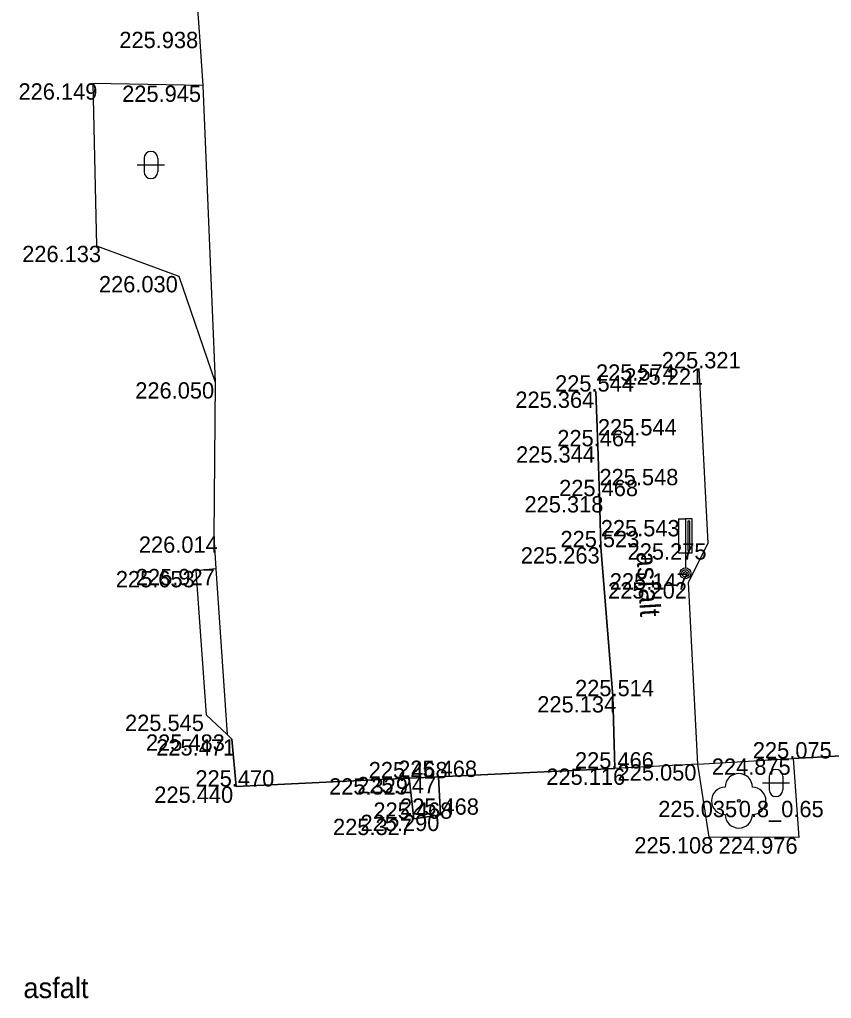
# Model space of a CAD drawing. Extents: x -599516 to -599132, y -1163668 to -1163119.
# Drawn here: x -599367.22 to -599352.29, y -1163237.29 to -1163219.3 of the extents above; entities that cross this region are included whole.
import ezdxf

# ---------------------------------------------------------------- set-up
doc = ezdxf.new("R2010")
doc.units = 0
for name, color, linetype in [('Bod-oznac1', 7, 'Continuous'), ('Bod-oznac2', 7, 'Continuous'), ('Bod-oznac3', 7, 'Continuous'), ('Bod-vyska1', 7, 'Continuous'), ('Bod-vyska2', 7, 'Continuous'), ('Bod-vyska3', 7, 'Continuous'), ('Z_cela-hrobu-dolni-linie', 7, 'Continuous'), ('Z_cela-hrobu-horni-linie', 7, 'Continuous'), ('Z_chodnik', 7, 'Continuous'), ('Z_komunikace', 7, 'Continuous'), ('Z_kultury-znacky', 7, 'Continuous'), ('Z_obvod-kmene-spodek-ve-vysce1_2m', 7, 'Continuous'), ('Z_popis-budov-povrchu', 7, 'Continuous'), ('Z_stromy-kere', 7, 'Continuous'), ('Z_zelen-obvod-zivy-plot', 7, 'Continuous'), ('Z_znacky-ostatni-orientacni-sloupek', 7, 'Continuous'), ('Z_zpevnene-plochy', 7, 'Continuous')]:
    doc.layers.add(name, color=color, linetype=linetype)

msp = doc.modelspace()

# ---------------------------------------------------------------- linework, layer by layer
at = {"layer": 'Bod-oznac1'}
for p, q in [((-599363.911, -1163219.523), (-599363.911, -1163219.523)), ((-599365.869, -1163220.47), (-599365.869, -1163220.47)), ((-599363.848, -1163220.511), (-599363.848, -1163220.511)), ((-599365.801, -1163223.457), (-599365.801, -1163223.457)), ((-599364.29, -1163224.012), (-599364.29, -1163224.012)), ((-599354.719, -1163225.709), (-599354.719, -1163225.709)), ((-599363.622, -1163225.965), (-599363.622, -1163225.965)), ((-599356.618, -1163226.136), (-599356.618, -1163226.136)), ((-599356.583, -1163227.142), (-599356.583, -1163227.142)), ((-599356.554, -1163228.058), (-599356.554, -1163228.058)), ((-599363.646, -1163228.799), (-599363.646, -1163228.799)), ((-599356.53, -1163228.997), (-599356.53, -1163228.997)), ((-599354.553, -1163228.925), (-599354.553, -1163228.925)), ((-599363.976, -1163229.434), (-599363.976, -1163229.434)), ((-599363.605, -1163229.396), (-599363.605, -1163229.396)), ((-599354.973, -1163229.475), (-599354.973, -1163229.475)), ((-599354.916, -1163229.641), (-599354.916, -1163229.641)), ((-599356.308, -1163231.735), (-599356.308, -1163231.735)), ((-599363.783, -1163232.075), (-599363.783, -1163232.075)), ((-599363.398, -1163232.438), (-599363.398, -1163232.438)), ((-599363.312, -1163232.527), (-599363.312, -1163232.527)), ((-599352.993, -1163232.88), (-599352.993, -1163232.88)), ((-599356.269, -1163233.065), (-599356.269, -1163233.065)), ((-599354.743, -1163232.987), (-599354.743, -1163232.987)), ((-599360.055, -1163233.244), (-599360.055, -1163233.244)), ((-599359.514, -1163233.22), (-599359.514, -1163233.22)), ((-599363.236, -1163233.396), (-599363.236, -1163233.396)), ((-599353.993, -1163233.659), (-599353.993, -1163233.659)), ((-599359.969, -1163233.988), (-599359.969, -1163233.988)), ((-599359.479, -1163233.914), (-599359.479, -1163233.914)), ((-599354.536, -1163234.326), (-599354.536, -1163234.326)), ((-599352.89, -1163234.332), (-599352.89, -1163234.332))]:
    msp.add_line(p, q, dxfattribs=at)
at = {"layer": 'Bod-oznac2'}
for p, q in [((-599354.719, -1163225.709), (-599354.719, -1163225.709)), ((-599356.618, -1163226.136), (-599356.618, -1163226.136)), ((-599356.583, -1163227.142), (-599356.583, -1163227.142)), ((-599356.554, -1163228.058), (-599356.554, -1163228.058)), ((-599356.53, -1163228.997), (-599356.53, -1163228.997)), ((-599356.308, -1163231.735), (-599356.308, -1163231.735)), ((-599352.993, -1163232.88), (-599352.993, -1163232.88)), ((-599356.269, -1163233.065), (-599356.269, -1163233.065)), ((-599360.055, -1163233.244), (-599360.055, -1163233.244)), ((-599359.514, -1163233.22), (-599359.514, -1163233.22)), ((-599363.236, -1163233.396), (-599363.236, -1163233.396)), ((-599359.969, -1163233.988), (-599359.969, -1163233.988)), ((-599359.479, -1163233.914), (-599359.479, -1163233.914))]:
    msp.add_line(p, q, dxfattribs=at)
at = {"layer": 'Bod-oznac3'}
for p, q in [((-599356.618, -1163226.136), (-599356.618, -1163226.136)), ((-599356.583, -1163227.142), (-599356.583, -1163227.142)), ((-599356.554, -1163228.058), (-599356.554, -1163228.058)), ((-599356.53, -1163228.997), (-599356.53, -1163228.997))]:
    msp.add_line(p, q, dxfattribs=at)
at = {"layer": 'Z_cela-hrobu-dolni-linie'}
for p, q in [((-599363.848, -1163220.511), (-599363.622, -1163225.965)), ((-599354.743, -1163232.987), (-599352.993, -1163232.88))]:
    msp.add_line(p, q, dxfattribs=at)
msp.add_lwpolyline([(-599359.514, -1163233.22), (-599360.055, -1163233.244)], dxfattribs=at)
at = {"layer": 'Z_cela-hrobu-horni-linie'}
msp.add_line((-599354.553, -1163228.925), (-599354.719, -1163225.709), dxfattribs=at)
for points in [[(-599363.312, -1163232.527), (-599363.236, -1163233.396), (-599360.055, -1163233.244), (-599359.514, -1163233.22), (-599356.269, -1163233.065), (-599356.308, -1163231.735), (-599356.53, -1163228.997), (-599356.53, -1163228.997), (-599356.554, -1163228.058), (-599356.554, -1163228.058), (-599356.583, -1163227.142), (-599356.583, -1163227.142), (-599356.618, -1163226.136), (-599356.618, -1163226.136)], [(-599354.743, -1163232.987), (-599352.993, -1163232.88), (-599348.121, -1163232.614), (-599348.121, -1163232.614)]]:
    msp.add_lwpolyline(points, dxfattribs=at)
at = {"layer": 'Z_chodnik'}
msp.add_line((-599354.743, -1163232.987), (-599354.916, -1163229.641), dxfattribs=at)
for points in [[(-599354.916, -1163229.641), (-599354.553, -1163228.925), (-599354.719, -1163225.709)], [(-599356.618, -1163226.136), (-599356.583, -1163227.142), (-599356.554, -1163228.058), (-599356.53, -1163228.997), (-599356.308, -1163231.735)], [(-599356.308, -1163231.735), (-599356.269, -1163233.065)]]:
    msp.add_lwpolyline(points, dxfattribs=at)
at = {"layer": 'Z_komunikace'}
msp.add_line((-599363.236, -1163233.396), (-599363.312, -1163232.527), dxfattribs=at)
for points in [[(-599364.81, -1163202.525), (-599364.713, -1163204.27), (-599364.649, -1163207.2), (-599364.55, -1163208.52), (-599365.622, -1163208.83), (-599366.647, -1163211.3), (-599366.029, -1163213.009), (-599364.308, -1163212.853), (-599364.108, -1163216.842), (-599363.911, -1163219.523), (-599363.848, -1163220.511), (-599365.869, -1163220.47), (-599365.801, -1163223.457), (-599364.29, -1163224.012), (-599363.622, -1163225.965), (-599363.646, -1163228.799), (-599363.605, -1163229.396), (-599363.398, -1163232.438), (-599363.312, -1163232.527)], [(-599348.121, -1163232.614), (-599352.993, -1163232.88), (-599352.89, -1163234.332), (-599354.536, -1163234.326), (-599354.743, -1163232.987), (-599356.269, -1163233.065), (-599359.514, -1163233.22), (-599359.479, -1163233.914), (-599359.969, -1163233.988), (-599360.055, -1163233.244), (-599363.236, -1163233.396)]]:
    msp.add_lwpolyline(points, dxfattribs=at)
at = {"layer": 'Z_kultury-znacky'}
for p, q in [((-599365.051, -1163221.971), (-599364.551, -1163221.971)), ((-599364.926, -1163221.846), (-599364.926, -1163222.096)), ((-599364.676, -1163221.846), (-599364.676, -1163222.096)), ((-599353.434, -1163233.205), (-599353.434, -1163233.455)), ((-599353.184, -1163233.205), (-599353.184, -1163233.455)), ((-599353.559, -1163233.33), (-599353.059, -1163233.33))]:
    msp.add_line(p, q, dxfattribs=at)
for centre, start, end in [((-599364.801, -1163221.846), 0, 180), ((-599364.801, -1163222.096), 180, 0), ((-599353.309, -1163233.206), 0, 180), ((-599353.309, -1163233.456), 180, 0)]:
    msp.add_arc(centre, 0.125, start, end, dxfattribs=at)
at = {"layer": 'Z_stromy-kere'}
msp.add_circle((-599353.993, -1163233.659), 0.025, dxfattribs=at)
for centre, start, end in [((-599353.993, -1163233.409), 0, 180), ((-599354.243, -1163233.659), 90, 270), ((-599353.743, -1163233.659), 270, 90), ((-599353.993, -1163233.909), 180, 0)]:
    msp.add_arc(centre, 0.25, start, end, dxfattribs=at)
at = {"layer": 'Z_zelen-obvod-zivy-plot'}
msp.add_lwpolyline([(-599363.605, -1163229.396), (-599363.976, -1163229.434), (-599363.783, -1163232.075), (-599363.398, -1163232.438)], dxfattribs=at)
at = {"layer": 'Z_znacky-ostatni-orientacni-sloupek'}
for p, q in [((-599355.098, -1163228.475), (-599355.098, -1163229.1)), ((-599355.098, -1163228.475), (-599354.973, -1163228.475)), ((-599355.098, -1163229.1), (-599354.973, -1163229.1)), ((-599354.973, -1163229.1), (-599354.973, -1163229.375))]:
    msp.add_line(p, q, dxfattribs=at)
for points in [[(-599354.973, -1163229.1), (-599354.848, -1163229.1), (-599354.848, -1163228.475), (-599354.973, -1163228.475)], [(-599354.931, -1163229.058), (-599354.89, -1163229.058), (-599354.89, -1163228.518), (-599354.931, -1163228.518)]]:
    msp.add_lwpolyline(points, close=True, dxfattribs=at)
for radius in [0.1, 0.065, 0.03]:
    msp.add_circle((-599354.973, -1163229.475), radius, dxfattribs=at)
at = {"layer": 'Z_zpevnene-plochy'}
msp.add_lwpolyline([(-599360.055, -1163233.244), (-599359.969, -1163233.988), (-599359.479, -1163233.914), (-599359.514, -1163233.22)], dxfattribs=at)

# ---------------------------------------------------------------- texts
at = {"layer": 'Bod-vyska1'}
for s, p in [('225.938', (-599365.381, -1163219.823)), ('226.149', (-599367.235, -1163220.77)), ('225.945', (-599365.329, -1163220.811)), ('226.133', (-599367.167, -1163223.757)), ('226.030', (-599365.756, -1163224.312)), ('225.221', (-599356.097, -1163226.009)), ('226.050', (-599365.088, -1163226.265)), ('225.364', (-599358.1, -1163226.436)), ('225.344', (-599358.087, -1163227.442)), ('225.318', (-599357.932, -1163228.358)), ('226.014', (-599365.022, -1163229.099)), ('225.263', (-599358, -1163229.297)), ('225.275', (-599356.036, -1163229.225)), ('225.653', (-599365.446, -1163229.734)), ('225.927', (-599365.077, -1163229.696)), ('225.147', (-599356.364, -1163229.775)), ('225.202', (-599356.396, -1163229.941)), ('225.134', (-599357.697, -1163232.035)), ('225.545', (-599365.276, -1163232.375)), ('225.483', (-599364.891, -1163232.738)), ('225.471', (-599364.703, -1163232.827)), ('224.875', (-599354.488, -1163233.18)), ('225.116', (-599357.531, -1163233.365)), ('225.050', (-599356.221, -1163233.287)), ('225.329', (-599361.525, -1163233.544)), ('225.247', (-599361.009, -1163233.52)), ('225.440', (-599364.738, -1163233.696)), ('225.035', (-599355.473, -1163233.959)), ('225.327', (-599361.452, -1163234.288)), ('225.290', (-599360.947, -1163234.214)), ('225.108', (-599355.912, -1163234.626)), ('224.976', (-599354.362, -1163234.632))]:
    msp.add_text(s, height=0.3, dxfattribs=at).set_placement(p)
at = {"layer": 'Bod-vyska2'}
for s, p in [('225.321', (-599355.408, -1163225.709)), ('225.544', (-599357.37, -1163226.136)), ('225.464', (-599357.329, -1163227.142)), ('225.468', (-599357.295, -1163228.058)), ('225.523', (-599357.271, -1163228.997)), ('225.514', (-599357.002, -1163231.735)), ('225.075', (-599353.734, -1163232.88)), ('225.466', (-599357.004, -1163233.065)), ('225.468', (-599360.796, -1163233.244)), ('225.468', (-599360.255, -1163233.22)), ('225.470', (-599363.982, -1163233.396)), ('225.468', (-599360.22, -1163233.914)), ('225.468', (-599360.71, -1163233.988))]:
    msp.add_text(s, height=0.3, dxfattribs=at).set_placement(p)
at = {"layer": 'Bod-vyska3'}
for s, p in [('225.574', (-599356.618, -1163225.936)), ('225.544', (-599356.583, -1163226.942)), ('225.548', (-599356.554, -1163227.858)), ('225.543', (-599356.53, -1163228.797))]:
    msp.add_text(s, height=0.3, dxfattribs=at).set_placement(p)
at = {"layer": 'Z_obvod-kmene-spodek-ve-vysce1_2m'}
msp.add_text('0.8_0.65', height=0.3, dxfattribs=at).set_placement((-599353.993, -1163233.959))
at = {"layer": 'Z_popis-budov-povrchu'}
msp.add_text('asfalt', height=0.375, rotation=273.4503, dxfattribs=at).set_placement((-599355.875, -1163229.087))
msp.add_text('asfalt', height=0.375, dxfattribs=at).set_placement((-599367.145, -1163237.285))

doc.saveas('drawing.dxf')
